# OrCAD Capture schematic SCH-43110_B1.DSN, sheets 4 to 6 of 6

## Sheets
4 3. MKW38A MCU: size C
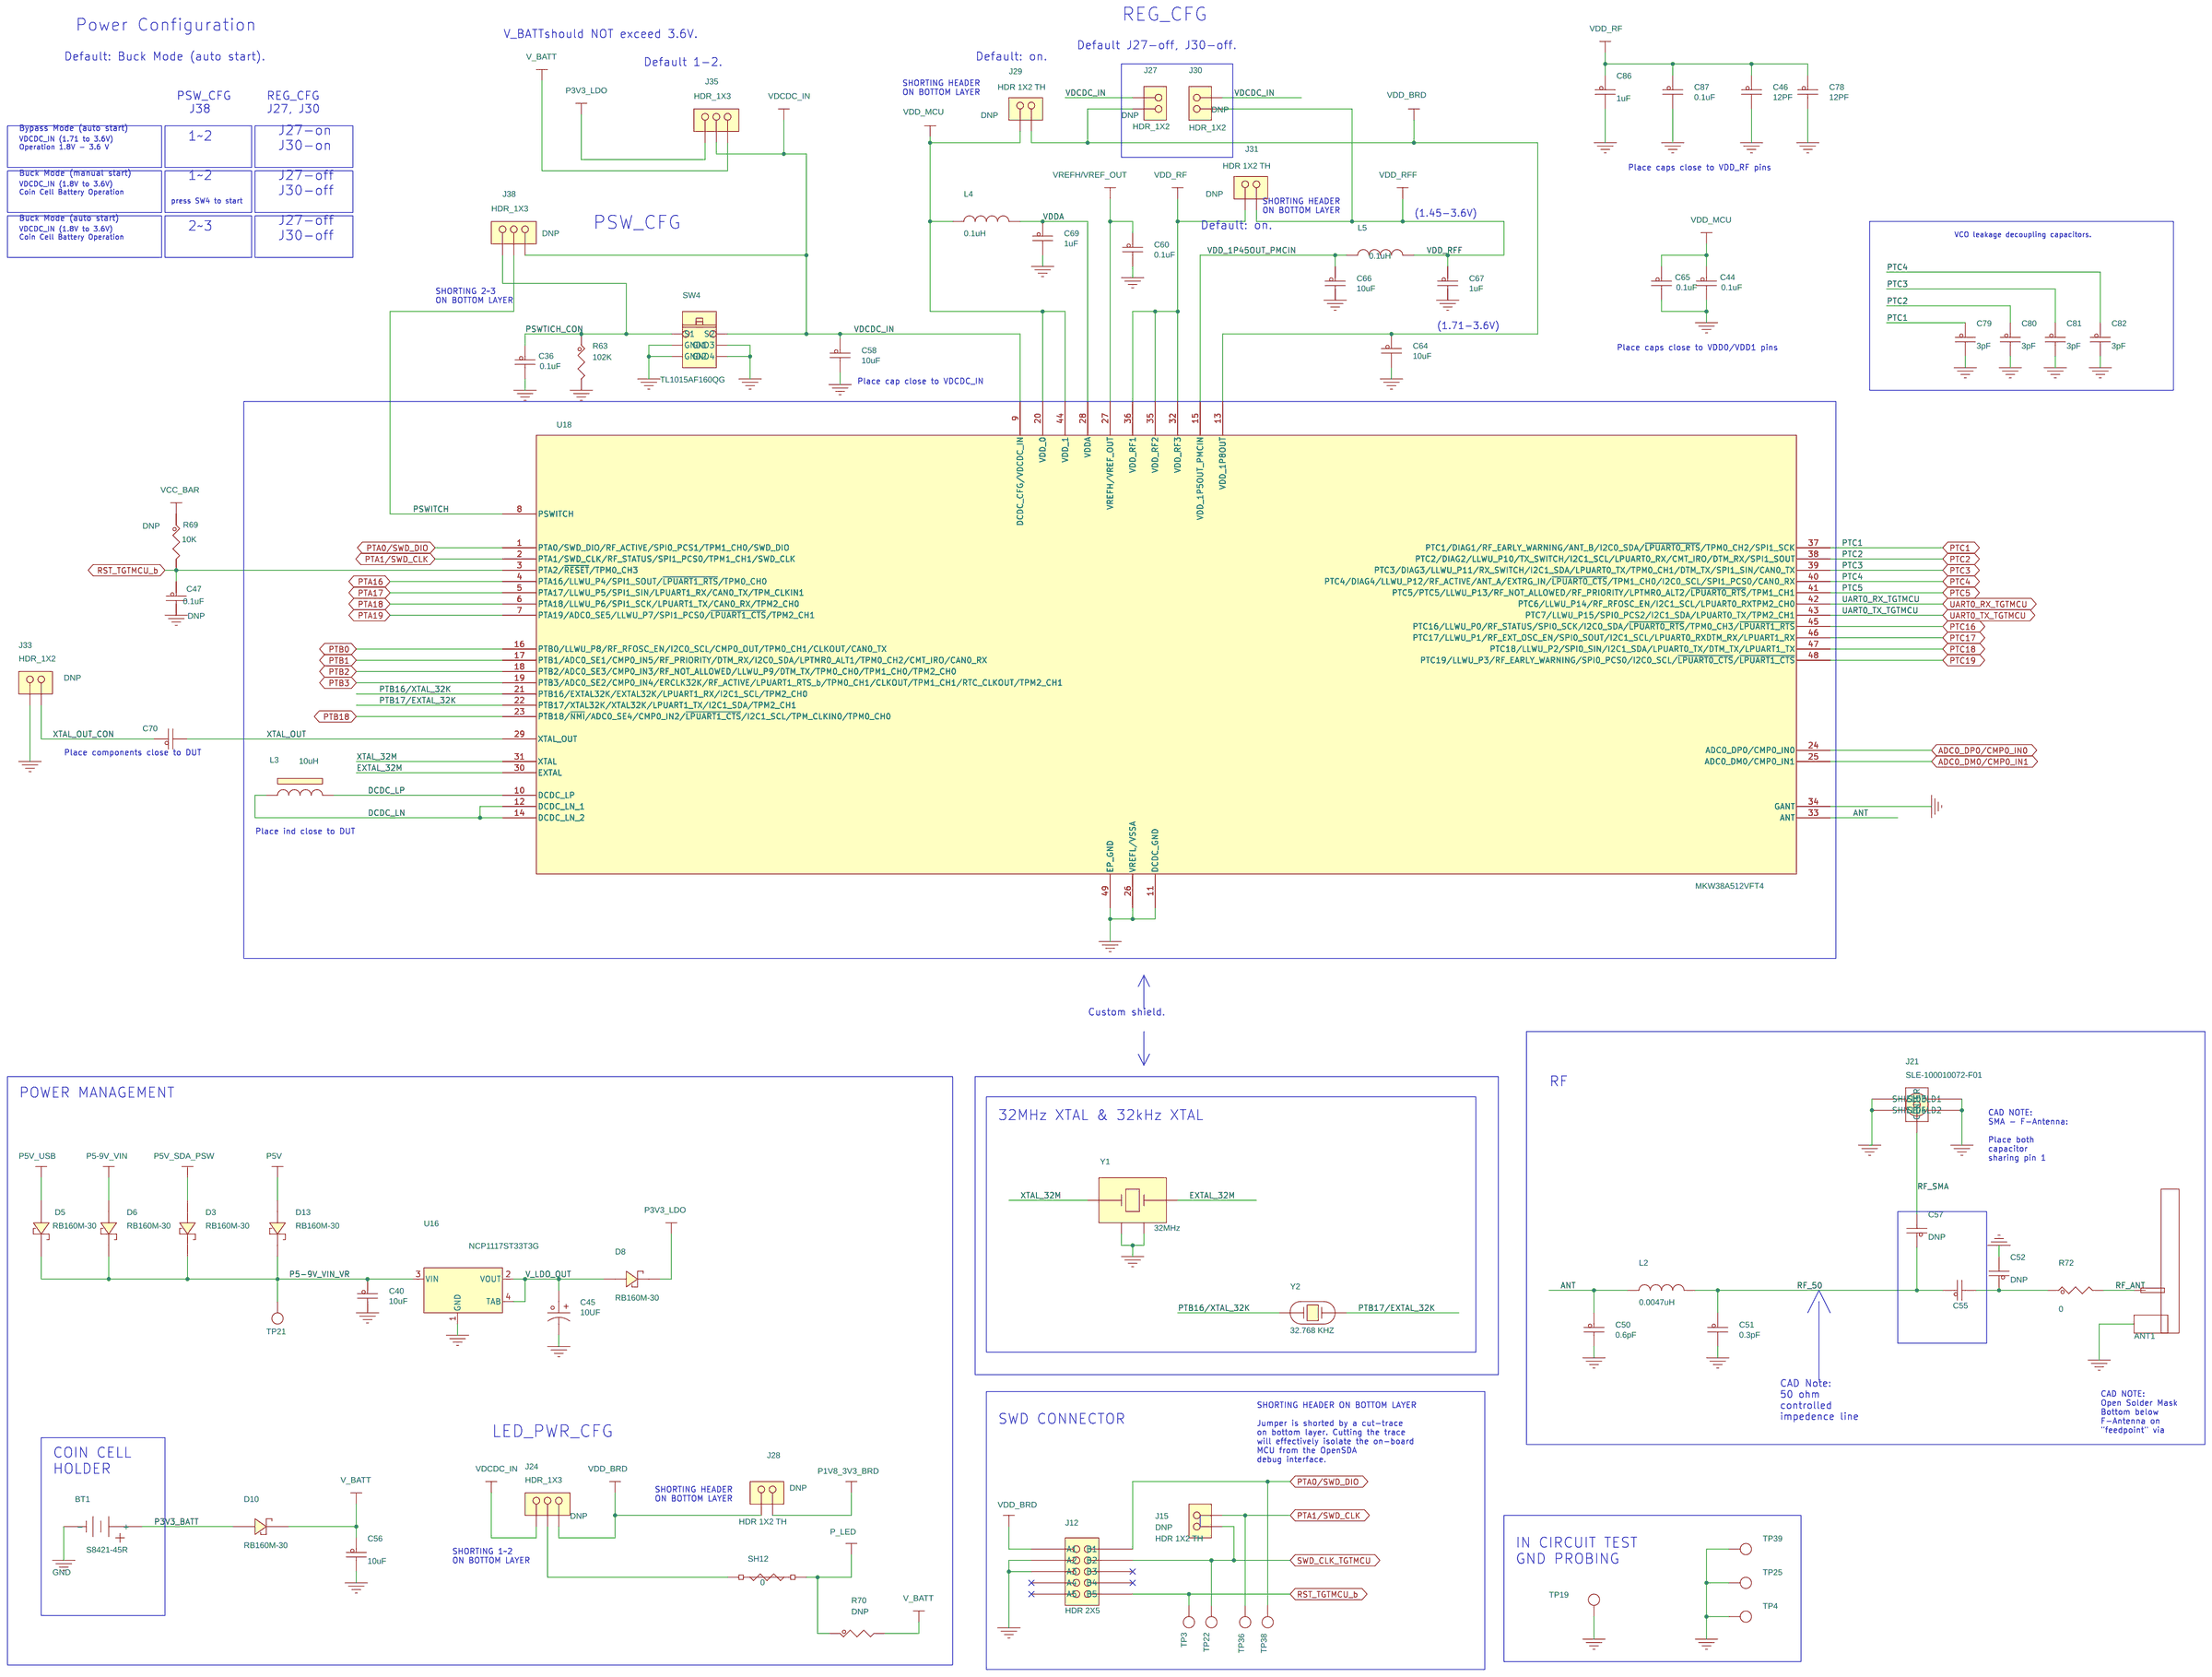
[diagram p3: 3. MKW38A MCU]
5 2. Block Diagram
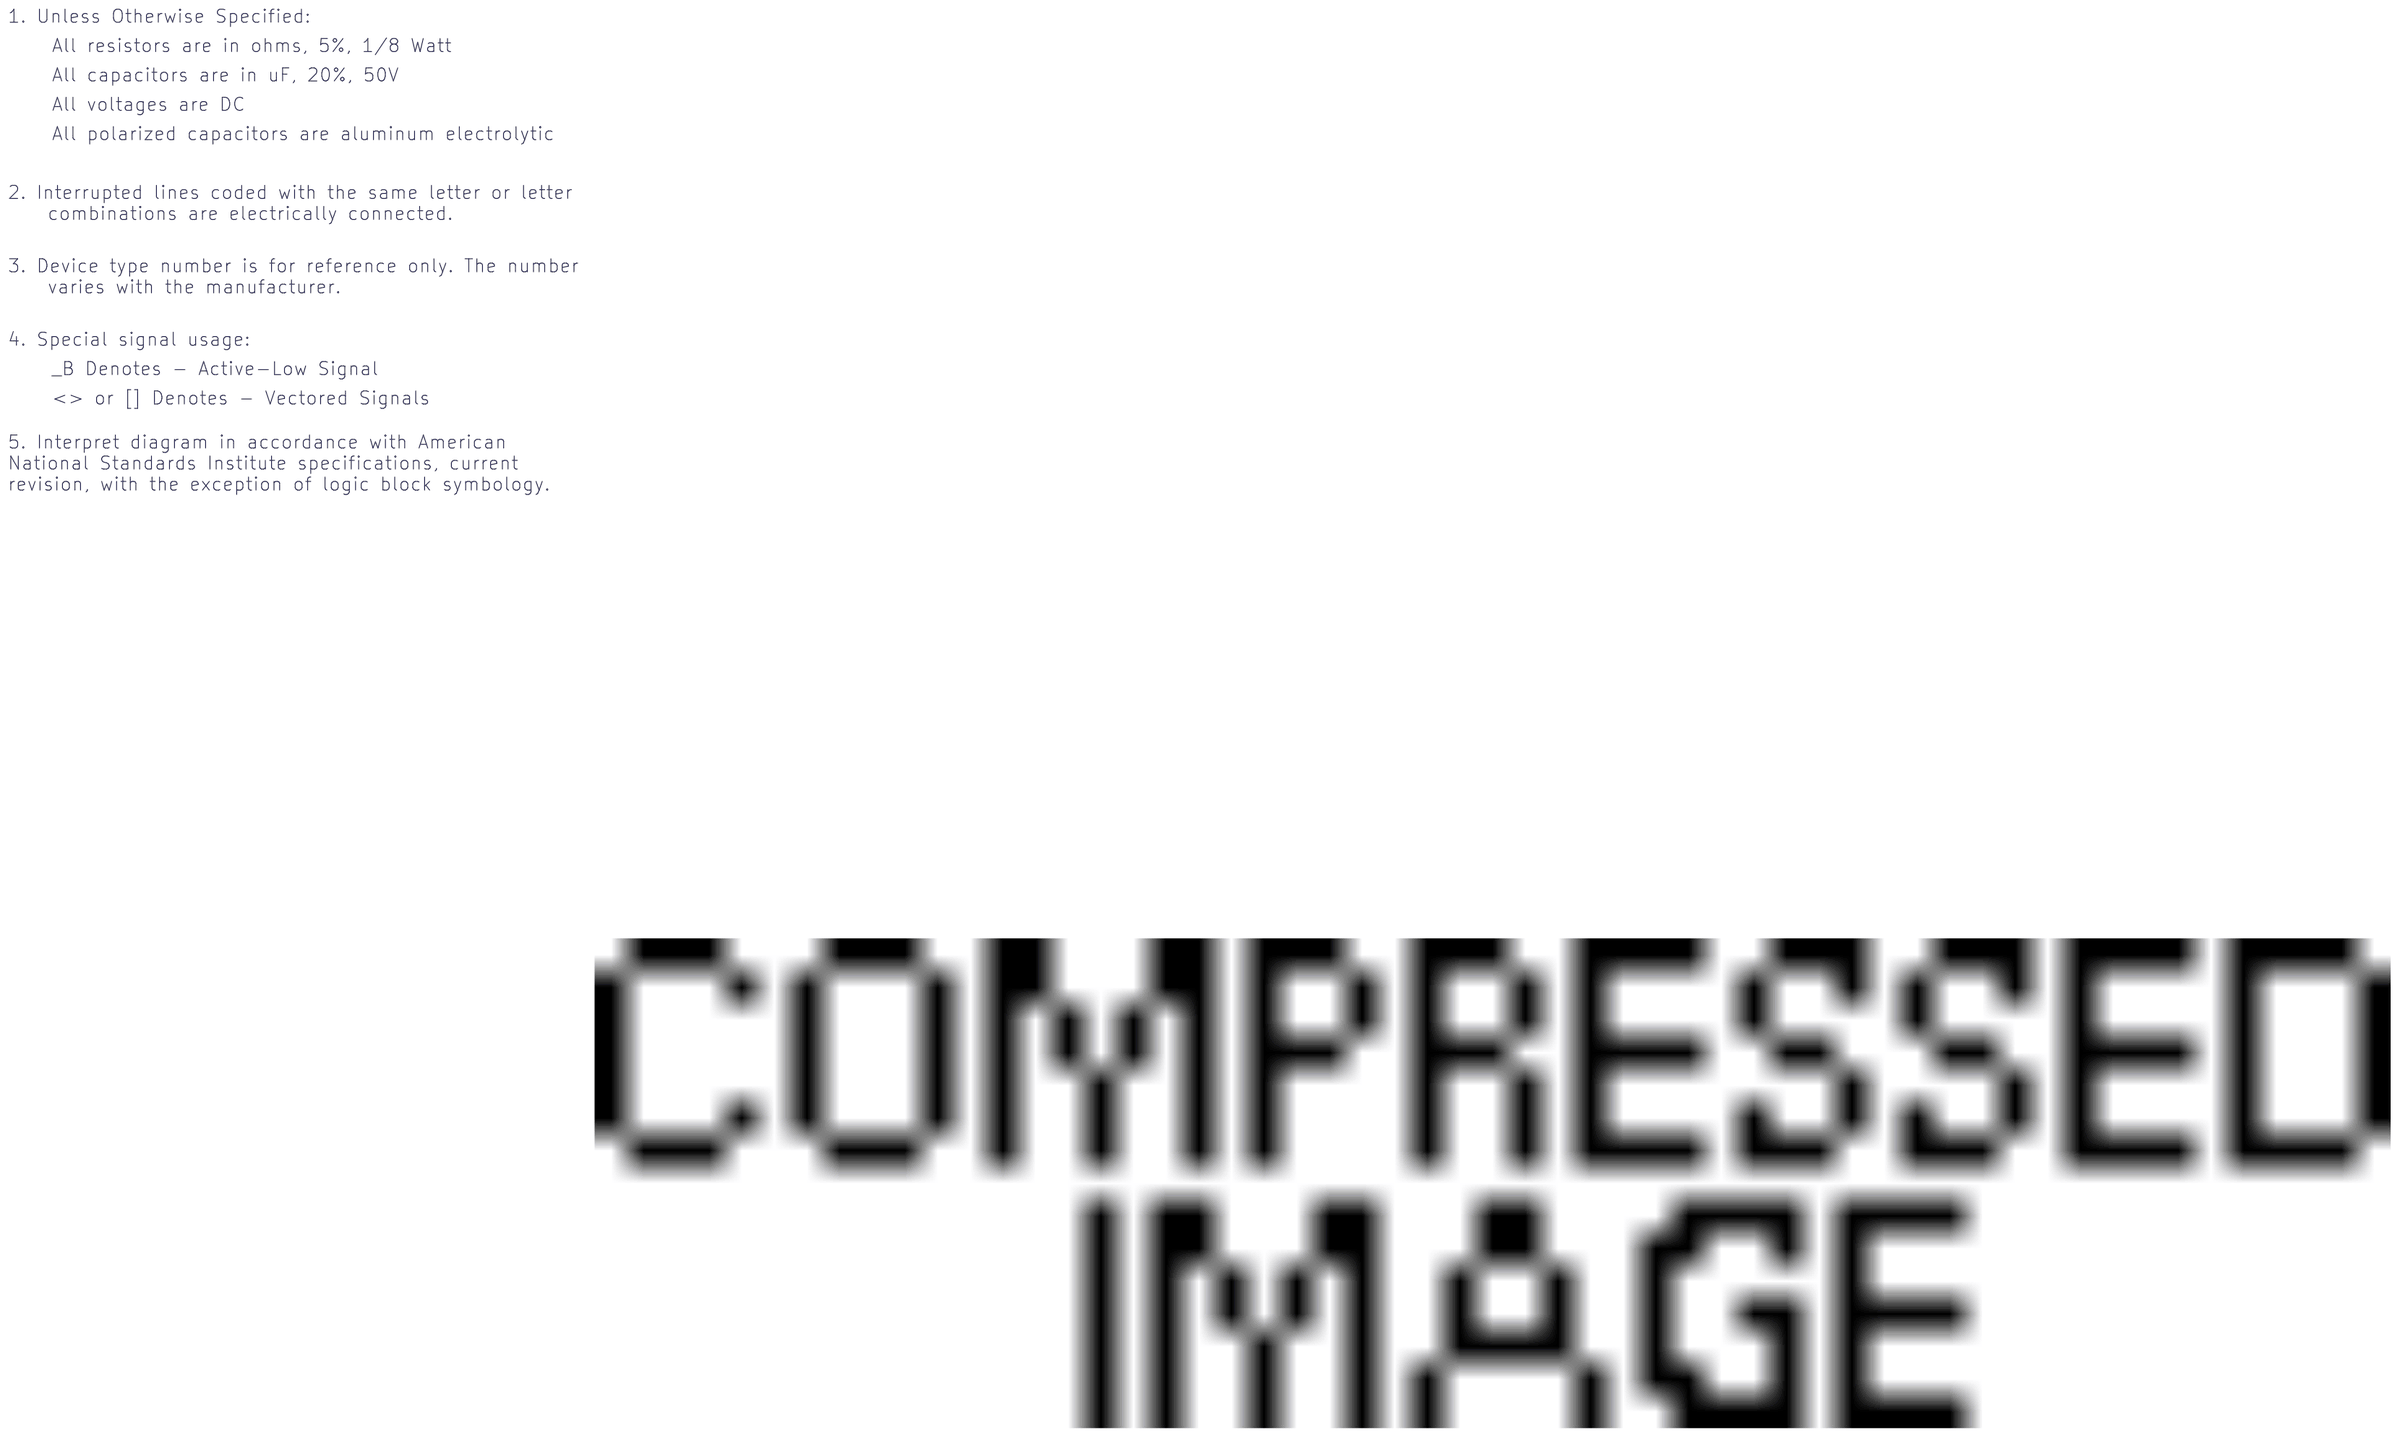
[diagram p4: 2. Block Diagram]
6 6. I/O Headers and Power Supply: size C
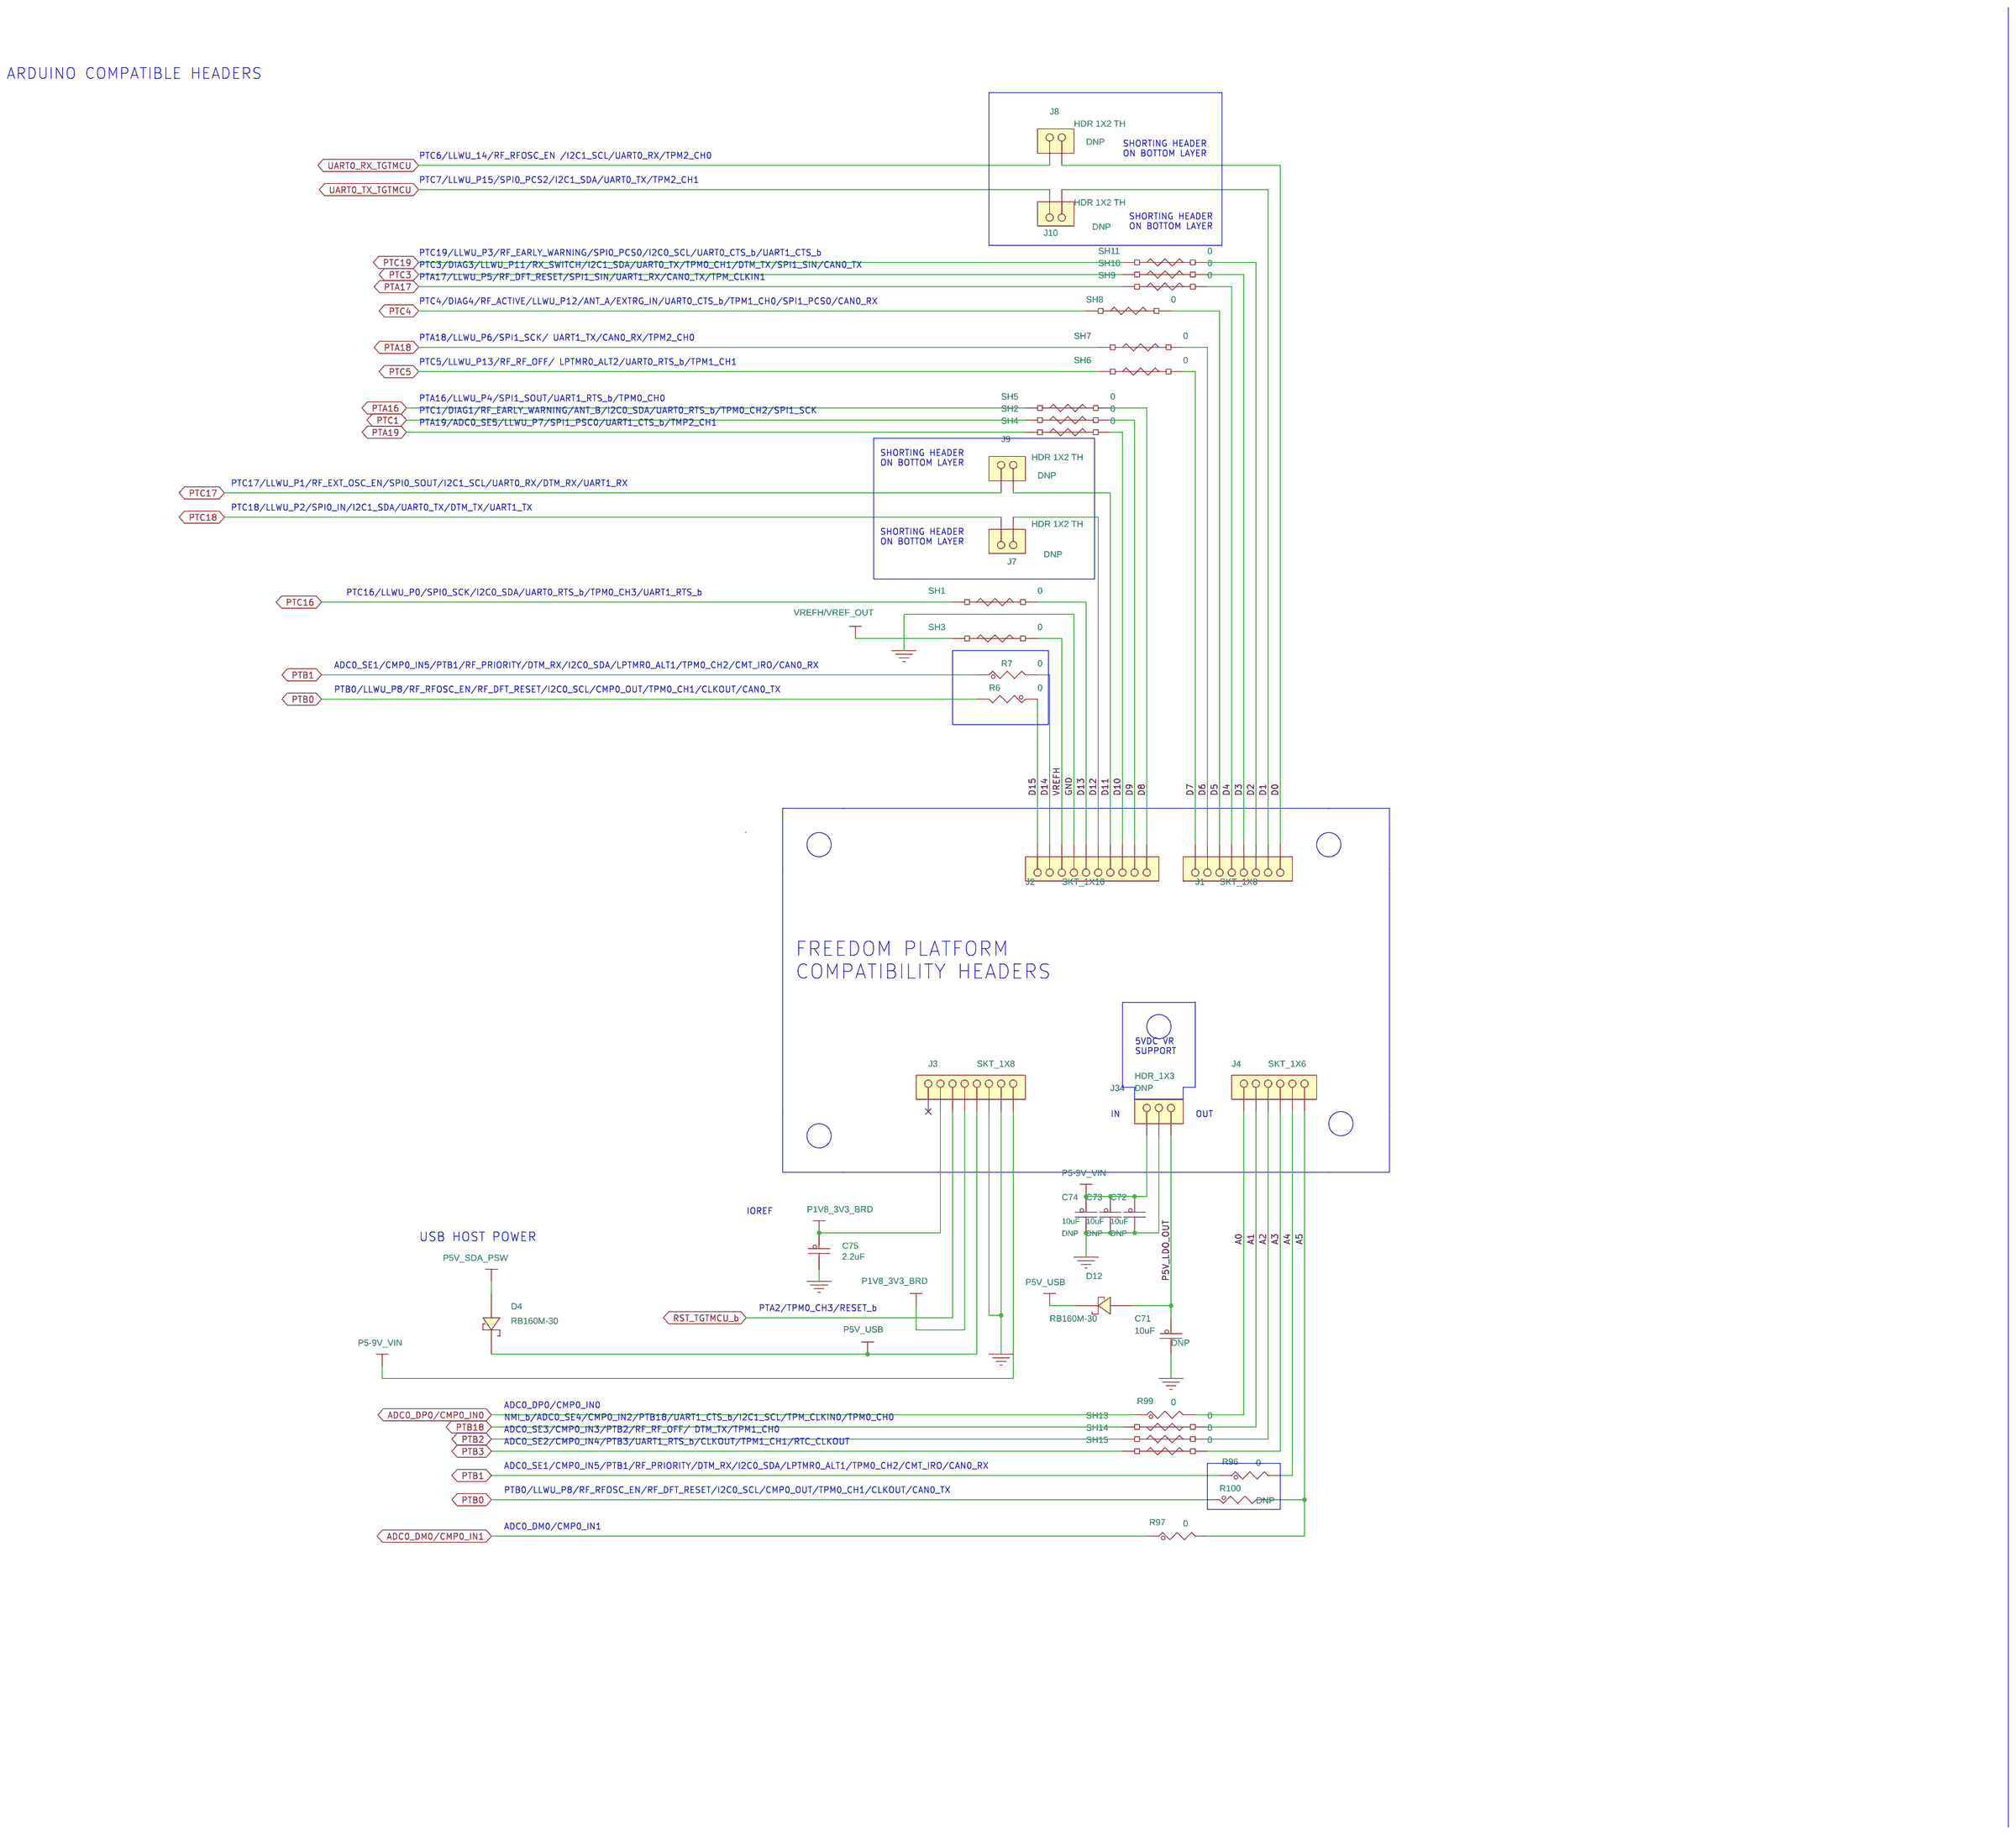
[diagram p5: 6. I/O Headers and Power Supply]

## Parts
sheet 3. MKW38A MCU
ANT1  F_Antenna  [f_antenna_dig528-2]
BT1  S8421-45R  [battery_holder_2032_sm]
C36  0.1uF  [CC0402_25]
C40  10uF  [CC0603_OV]
C44  0.1uF  [CC0402_25]
C45  10UF  [CC3216]
C46  12PF  [CC0402_25]
C47  0.1uF  [CC0402_25]
C50  0.6pF  [CC0402_25]
C51  0.3pF  [CC0402_25]
C52  10PF  [CC0402_25]
C55  10PF  [CC0402_25]
C56  10uF  [CC0603_OV]
C57  10PF  [CC0402_25]
C58  10uF  [CC0603_OV]
C60  0.1uF  [CC0402_25]
C64  10uF  [CC0603_OV]
C65  0.1uF  [CC0402_25]
C66  10uF  [CC0603_OV]
C67  1uF  [CC0402_25]
C69  1uF  [CC0402_25]
C70  10PF  [CC0402_25]
C78  12PF  [CC0402_25]
C79  3pF  [CC0402_25]
C80  3pF  [CC0402_25]
C81  3pF  [CC0402_25]
C82  3pF  [CC0402_25]
C86  1uF  [CC0402_25]
C87  0.1uF  [CC0402_25]
D3  RB160M-30  [pmdu_sod123]
D5  RB160M-30  [pmdu_sod123]
D6  RB160M-30  [pmdu_sod123]
D8  RB160M-30  [pmdu_sod123]
D10  RB160M-30  [pmdu_sod123]
D13  RB160M-30  [pmdu_sod123]
J12  HDR 2X5  [hdr_2X5_6x3_1p27mm_th]
J15  HDR 1X2 TH  [SH_HDR102_BOTTOM]
J21  SLE-100010072-F01  [con5_sma_7sq_sm]
J24  HDR_1X3  [HDR103]
J27  HDR_1X2  [hdr_1x2_2p54mm]
J28  HDR 1X2 TH  [SH_HDR102_BOTTOM]
J29  HDR 1X2 TH  [SH_HDR102_BOTTOM]
J30  HDR_1X2  [hdr_1x2_2p54mm]
J31  HDR 1X2 TH  [SH_HDR102_BOTTOM]
J33  HDR_1X2  [hdr_1x2_2p54mm]
J35  HDR_1X3  [HDR103]
J38  HDR_1X3  [HDR103]
L2  0.0047uH  [IND_0402]
L3  10uH  [ind_vls4012e]
L4  0.1uH  [IND_0402]
L5  0.1uH  [IND_0402]
R63  102K  [RC0402_25]
R69  10K  [RC0402_25]
R70  0  [RC0402_25]
R72  0  [RC0402_25]
SH12  0  [SH0603]
SW4  TL1015AF160QG  [sw2_spst_4x3_sm]
TP3  TPAD_030  [TPAD_030]
TP4  TPAD_030  [TPAD_030]
TP19  TESTLOOP_BLACK  [tp_th_063]
TP21  TPAD_040  [TPAD_040]
TP22  TPAD_030  [TPAD_030]
TP25  TPAD_030  [TPAD_030]
TP36  TPAD_030  [TPAD_030]
TP38  TPAD_030  [TPAD_030]
TP39  TPAD_030  [TPAD_030]
U16  NCP1117ST33T3G  [sot223]
U18  MKW38A512VFT4  [qfn_48_0p5_7x7_5p7ep]
Y1  32MHz  [xtal4_2p1x1p7mm_sm]
Y2  32.768 KHZ  [XTAL2-3P2X1P5-SM]
sheet 6. I/O Headers and Power Supply
C71  10uF  [CC0603_OV]
C72  10uF  [CC0603_OV]
C73  10uF  [CC0603_OV]
C74  10uF  [CC0603_OV]
C75  2.2uF  [CC0603_OV]
D4  RB160M-30  [pmdu_sod123]
D12  RB160M-30  [pmdu_sod123]
J1  SKT_1X8  [con_1x8_skt_2p54_th]
J2  SKT_1X10  [con_skt1x10_th]
J3  SKT_1X8  [con_1x8_skt_2p54_th]
J4  SKT_1X6  [con_skt1x6_th]
J7  HDR 1X2 TH  [SH_HDR102_BOTTOM]
J8  HDR 1X2 TH  [SH_HDR102_BOTTOM]
J9  HDR 1X2 TH  [SH_HDR102_BOTTOM]
J10  HDR 1X2 TH  [SH_HDR102_BOTTOM]
J34  HDR_1X3  [HDR103]
R6  0  [RC0603_OV]
R7  0  [RC0603_OV]
R96  0  [RC0603_OV]
R97  0  [RC0603_OV]
R99  0  [RC0603_OV]
R100  0  [RC0402_25]
SH1  0  [SH0402]
SH2  0  [SH0402]
SH3  0  [SH0402]
SH4  0  [SH0402]
SH5  0  [SH0402]
SH6  0  [SH0402]
SH7  0  [SH0402]
SH8  0  [SH0402]
SH9  0  [SH0402]
SH10  0  [SH0402]
SH11  0  [SH0402]
SH13  0  [SH0402]
SH14  0  [SH0402]
SH15  0  [SH0402]

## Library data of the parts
ANT1 = F_Antenna: PCB F ANTENNA, NO PART ORDER; AGILE_PN: 510-75678; CAD_APPROVED: Yes; HEIGHT: 0MM; MFG_NAME01: NOT A PART; MFG_PN01: NOT A PART; ROHS: Yes
BT1 = BATTERY: BATTERY HOLDER CR2032 SMD; AGILE_PN: 801-76278; CAD_APPROVED: Yes; HEIGHT: 5.5 MM; MFG_NAME01: HARWIN INC; Package Type: SMT; ROHS: Yes; Temp Range: -40° C to +105° C; Temp_Range: -40° C to +105° C
C36 C44 C60 C65 C87 = CAP_NP: CAP CER 0.1uF 50V 10% X7R 0402; AGILE_PN: 150-79069; CAD_APPROVED: Yes; FPLIST: CC0402_25,CC0402_HD,0402_CC; HEIGHT: 0.55MM; MFG_NAME01: TDK; MFG_PN01: C1005X7R1H104K050BE; ROHS: Yes; Tolerance: 10%; VOLTAGE: 50V
C40 C56 C58 C64 C66 = CAP_NP: CAP CER 10uF 16V 20% X5R 0603; AGILE_PN: 150-79092; CAD_APPROVED: Yes; FPLIST: CC0603_OV,CC0603,0603_CC; HEIGHT: 1mm; MFG_NAME01: TAIYO YUDEN; MFG_PN01: EMK107BBJ106MA-T; ROHS: Yes; Tolerance: 20%; VOLTAGE: 16V
C45 = CAP_POL: CAP TANT ESR=0.900 OHMS 10UF 10V 20% -- 3216-18; AGILE_PN: 150-75257; CAD_APPROVED: Yes; HEIGHT: 1.8MM; MFG_NAME01: AVX; MFG_PN01: TPSA106M010R0900; Package Size: 3216-18; Package Type: 7" T/R; ROHS: Yes; Tolerance: 20%; VOLTAGE: 10V
C46 C78 = CAP_NP: CAP CER 12PF 50V 5% C0G 0402; AGILE_PN: 150-75680; CAD_APPROVED: Yes; FPLIST: CC0402_25,CC0402_HD,0402_CC; HEIGHT: 0.55MM; MFG_NAME01: NIC COMPONENTS CORP; MFG_PN01: NMC0402NPO120J50TRPF; ROHS: Yes; Tolerance: 5%; VOLTAGE: 50V
C47 = CAP_NP: CAP CER 0.1uF 50V 10% X7R 0402; AGILE_PN: 150-79069; ASSY_OPT: DNP; CAD_APPROVED: Yes; FPLIST: CC0402_25,CC0402_HD,0402_CC; HEIGHT: 0.55MM; MFG_NAME01: TDK; MFG_PN01: C1005X7R1H104K050BE; ROHS: Yes; Tolerance: 10%; VOLTAGE: 50V
C50 = CAP_NP: CAP CER 0.6pF 50V 0.1pF C0G AEC-Q200 0402; AGILE_PN: 150-80681; CAD_APPROVED: Yes; FPLIST: CC0402_25,CC0402_HD,0402_CC; HEIGHT: 0.55MM; MFG_NAME01: Murata; MFG_PN01: GCM1555C1HR60BA16; Package Size: 0402; ROHS: Yes; Temp Range: -55°C to +125°C; Temp_Range: -55°C to +125°C; Tolerance: 0.1pF; VOLTAGE: 50V
C51 = CAP_NP: CAP CER 0.3pF 50V 0.1pF C0G AEC-Q200 0402; AGILE_PN: 150-80775; CAD_APPROVED: Yes; FPLIST: CC0402_25,CC0402_HD,0402_CC; HEIGHT: 0.55MM; MFG_NAME01: Murata Electronics; MFG_PN01: GCM1555C1HR30BA16D; Package Size: 0402 (1005 Metric); Package Type: Surface Mount, MLCC; ROHS: Yes; Rated Voltage: 50V; Temp Range: -55°C to +125°C; Tolerance: 0.1pF
C52 C57 = CAP_NP: CAP CER 10PF 50V 5% C0G 0402; AGILE_PN: 150-75265; ASSY_OPT: DNP; CAD_APPROVED: YES; FPLIST: CC0402_25,CC0402_HD,0402_CC; HEIGHT: 0.635MM; MFG_NAME01: AVX; MFG_PN01: 04025A100JAT2A; Package Size: 0402; Package Type: 7; ROHS: Yes; TOL: 5%; Tolerance: 5%; VOLTAGE: 50V
C55 C70 = CAP_NP: CAP CER 10PF 50V 5% C0G 0402; AGILE_PN: 150-75265; CAD_APPROVED: YES; FPLIST: CC0402_25,CC0402_HD,0402_CC; HEIGHT: 0.635MM; MFG_NAME01: AVX; MFG_PN01: 04025A100JAT2A; Package Size: 0402; Package Type: 7; ROHS: Yes; TOL: 5%; Tolerance: 5%; VOLTAGE: 50V
C67 C69 C86 = CAP_NP: CAP CER 1uF 25V 10% X6S AEC-Q200 0402; AGILE_PN: 150-80570; CAD_APPROVED: Yes; FPLIST: CC0402_25,CC0402_HD,0402_CC; HEIGHT: 0.6MM; MFG_NAME01: MURATA; MFG_PN01: GRT155C81E105KE13D; Package Size: 1.1x0.6x0.6MM; Package Type: 0402; ROHS: Yes; Temp Range: -55°C to +105°C; Temp_Range: -55°C to +105°C; Tolerance: 10%; VOLTAGE: 25V
C79-C82 = CAP_NP: CAP CER 3pF 50V ±0.25pF C0G AEC-Q200 0402; AGILE_PN: 150-80781; CAD_APPROVED: YES; FPLIST: CC0402_25,CC0402_HD,0402_CC; HEIGHT: 0.55 MM; MFG_NAME01: Murata Electronics; MFG_PN01: GCQ1555C1H3R0CB01D; Package Size: 0402 (1005 Metric); Package Type: Surface Mount, MLCC; ROHS: YES; Rated Voltage: 50V; Tolerance: 0.25pF
D3-D6 D8 D10 D12 D13 = DIODE_SCHTKY: DIODE SCH 1A 30V SOD123; AGILE_PN: 480-79681; CAD_APPROVED: Yes; HEIGHT: 0.9MM; MFG_NAME01: ROHM; MFG_PN01: RB160M-30TR; ROHS: Yes
J12 = CONN_HDR_5X2: HDR 2X5 TH 50MIL CTR 264H AU 91L; AGILE_PN: 210-81148; CAD_APPROVED: Yes; HEIGHT: 6.7MM; MFG_NAME01: LIANYI DIANZI; MFG_PN01: 333210S1411; ROHS: Yes
J7-J10 J15 J28 J29 J31 = CONN_HDR_2X1: HDR 1X2 TH 100MIL SP 339H AU 98L; AGILE_PN: 210-75439; ASSY_OPT: DNP; CAD_APPROVED: YES; FPLIST: HDR102,SH_HDR102_BOTTOM; HEIGHT: 8.71 MM; MFG_NAME01: SAMTEC; MFG_PN01: TSW-102-07-G-S; ROHS: Yes; Temp Range: -55°C to +125°C; Temp_Range: -55°C to +125°C
J21 = CONN_COAX_1P_F: CON 1 JACK SMA SKT 50 OHM SMT -- 418H AU; AGILE_PN: 211-79911; CAD_APPROVED: Yes; HEIGHT: 10.6MM; MFG_NAME01: DONGGUAN SENLING INDUSTRIAL CO. LTD; Package Type: SMA; ROHS: Yes
J24 J34 J38 = CONN_HDR_3X1: HDR 1X3 TH 100MIL SP 350H AU 118L; AGILE_PN: 210-81176; ASSY_OPT: DNP; CAD_APPROVED: Yes; HEIGHT: 8.9MM; MFG_NAME01: LIANYI DIANZI; MFG_PN01: 313103S1411; Package Size: 7p62x2p54x8p9mm; Package Type: TH; ROHS: Yes
J27 J30 J33 = CONN_HDR_2X1: HDR 1X2 TH 100MIL SP 347H AU 118L; AGILE_PN: 210-81145; ASSY_OPT: DNP; CAD_APPROVED: Yes; HEIGHT: 8.8 MM; MFG_NAME01: LIANYI DIANZI; MFG_PN01: 313102S1411; ROHS: Yes
J35 = CONN_HDR_3X1: HDR 1X3 TH 100MIL SP 350H AU 118L; AGILE_PN: 210-81176; CAD_APPROVED: Yes; HEIGHT: 8.9MM; MFG_NAME01: LIANYI DIANZI; MFG_PN01: 313103S1411; Package Size: 7p62x2p54x8p9mm; Package Type: TH; ROHS: Yes
L2 = INDUCTOR: IND -- 0.0047uH@100MHZ 700mA +/-0.3nH AEC-Q200 0402; AGILE_PN: 180-79018; CAD_APPROVED: Yes; FPLIST: IND_0402,0402_CC; HEIGHT: 0.55MM; MFG_NAME01: MURATA; MFG_PN01: LQG15HH4N7S02; ROHS: Yes; Temp Range: -55&#8451; to 125&#8451;; Temp_Range: -55&#8451; to 125&#8451;
L3 = IND_FERRITE: IND WW FER 10uH@1MHz 0.99A 20% 4012; AGILE_PN: 180-78215; CAD_APPROVED: Yes; HEIGHT: 1.2MM; MFG_NAME01: TDK; MFG_PN01: VLS4012ET-100M; PART_TYPE: FERRITE\BEAD; ROHS: Yes
L4 L5 = INDUCTOR: IND -- 0.1uH@100MHz 120mA 5% AEC-Q200 0402; AGILE_PN: TMP-CIP-2337; CAD_APPROVED: Yes; FPLIST: IND_0402,0402_CC; HEIGHT: 0.6MM; MFG_NAME01: MURATA; MFG_PN01: LQW15ANR10J0Z; PRE_APN: 180-79128; ROHS: Yes
R63 = RES: RES MF 102K 1/16W 1% HF 0402; AGILE_PN: 470-81192; CAD_APPROVED: Yes; FPLIST: RC0402_25,RC0402_HD,0402_CC; HEIGHT: 0.40 MM; MFG_NAME01: YAGEO AMERICA; MFG_PN01: RC0402FR-07102KL; ROHS: Yes; Tolerance: 1%; VOLTAGE: 50V
R69 = RES: RES MF 10K 1/16W 1% 0402; AGILE_PN: 470-80452; ASSY_OPT: DNP; CAD_APPROVED: Yes; FPLIST: RC0402_25,RC0402_HD,0402_CC; HEIGHT: 0.40 MM; MFG_NAME01: NIC COMPONENTS CORP; MFG_PN01: NRCL04F1002TRF; ROHS: Yes; Tolerance: 1%
R70 R100 = RES: RES MF ZERO OHM 1/16W 5% 0402; AGILE_PN: 470-75394; ASSY_OPT: DNP; CAD_APPROVED: Yes; FPLIST: RC0402_25,RC0402_HD,RC0402_X2,0402_CC; HEIGHT: 0.45 MM; MFG_NAME01: ROHM; MFG_PN01: MCR01MZPJ000; ROHS: Yes; Tolerance: 5%; VOLTAGE: 1/16W
R72 = RES: RES MF ZERO OHM 1/16W 5% 0402; AGILE_PN: 470-75394; CAD_APPROVED: Yes; FPLIST: RC0402_25,RC0402_HD,RC0402_X2,0402_CC; HEIGHT: 0.45 MM; MFG_NAME01: ROHM; MFG_PN01: MCR01MZPJ000; ROHS: Yes; Tolerance: 5%; VOLTAGE: 1/16W
SH12 = RES_SHORT-2: ZERO OHM CUT TRACE 0603 PADS; NO PART TO ORDER; AGILE_PN: 470-80018; CAD_APPROVED: Yes; FPLIST: SH0603,SH0603_CC,SH0603-X2_PIN1TO2,SH0603-X2_PIN2TO3; HEIGHT: 0.1MM; MFG_NAME01: LAYOUT ELEMENT ONLY; MFG_PN01: LAYOUT ELEMENT ONLY; ROHS: Yes
SW4 = SW_SPNO_2P_GND6P: SW SPST PB 50MA 12V SMT; AGILE_PN: 510-77720; CAD_APPROVED: Yes; HEIGHT: 2.4MM; MFG_NAME01: E SWITCH; ROHS: Yes
TP3 TP4 TP22 TP25 TP36 TP38 TP39 = TESTLOOP: TEST POINT PAD 30MIL DIA SMT, NO PART TO ORDER; AGILE_PN: 211-76642; CAD_APPROVED: Yes; HEIGHT: 0.1MM; MFG_NAME01: NOTACOMPONENT; MFG_PN01: NOTACOMPONENT; ROHS: Yes
TP19 = TESTLOOP: TEST POINT PC MULTI PURPOSE BLK TH; AGILE_PN: 210-79450; CAD_APPROVED: Yes; HEIGHT: 8.13MM; MFG_NAME01: KEYSTONE ELECTRONICS; MFG_PN01: 5011; ROHS: Yes
TP21 = TESTLOOP: TEST POINT PAD 40MIL DIA SMT, NO PART TO ORDER; AGILE_PN: 211-76643; CAD_APPROVED: Yes; HEIGHT: 0.1MM; MFG_NAME01: NOTACOMPONENT; MFG_PN01: NOTACOMPONENT; ROHS: Yes
U16 = LD1117AS18: IC VREG LDO 1A 3.3V SOT223; AGILE_PN: 312-80039; CAD_APPROVED: Yes; HEIGHT: 1.8MM; MFG_NAME01: ON SEMICONDUCTOR; ROHS: Yes; Temp Range: 0°C to +125°C; Temp_Range: 0°C to +125°C; VOLTAGE: 3.3V
U18 = MKW38A512VFT4_QFN48: IC MCU 2.4GHZ 512KB FLASH 48 MHz 1.71-3.6V QFN48; AGILE_PN: TMP-WF-34657; CAD_APPROVED: Yes; HEIGHT: 1 MM; MFG_NAME01: NXP SEMICONDUCTORS; PRE_APN: 344-02346; ROHS: Yes; VOLTAGE: 1.71-3.6V
Y1 = XTAL_13: XTAL 32MHz AEC0Q200 SMD 2016; AGILE_PN: 230-78273; CAD_APPROVED: Yes; HEIGHT: 0.5MM; MFG_NAME01: NDK; MFG_PN01: NX2016SA EXS00A-CS11775; ROHS: Yes; Temp Range: -40 to +125C; Temp_Range: -40 to +125C
Y2 = XTAL: XTAL 32.768kHZ FIXED -- AEC-Q200 SMT 3.2X1.5MM; AGILE_PN: 230-78318; CAD_APPROVED: Yes; HEIGHT: 0.9MM; MFG_NAME01: NDK; MFG_PN01: NX3215SA 32.768KHz EXS00A-MU01218; ROHS: Yes; Temp Range: -40 to 125C; Temp_Range: -40 to 125C
C71-C74 = CAP_NP: CAP CER 10uF 16V 20% X5R 0603; AGILE_PN: 150-79092; ASSY_OPT: DNP; CAD_APPROVED: Yes; FPLIST: CC0603_OV,CC0603,0603_CC; HEIGHT: 1mm; MFG_NAME01: TAIYO YUDEN; MFG_PN01: EMK107BBJ106MA-T; ROHS: Yes; Tolerance: 20%; VOLTAGE: 16V
C75 = CAP_NP: CAP CER 2.2UF 16V 10% X5R 0603; AGILE_PN: 150-75417; CAD_APPROVED: YES; FPLIST: CC0603_OV,CC0603,0603_CC; HEIGHT: 0.9 MM; MFG_NAME01: CAPAX TECHNOLOGIES INC.; MFG_PN01: 0603B225K160SNT; Package Size: 0603; ROHS: Yes; Tolerance: 10%; VOLTAGE: 16V
J1 J3 = CONN_HDR_8X1: CON 1X8 SKT TH 100MIL SP 343H AU 126L; AGILE_PN: 210-81494; CAD_APPROVED: Yes; HEIGHT: 8.7MM; MFG_NAME01: LIANYI DIANZI; MFG_PN01: 218108S1411; ROHS: Yes; Temp Range: -40C to +105C; Temp_Range: -40C to +105C
J2 = CONN_HDR_10X1: CON 1X10 SKT TH 100MIL SP 343H AU 126L; AGILE_PN: 210-81493; CAD_APPROVED: Yes; HEIGHT: 8.7MM; MFG_NAME01: LIANYI DIANZI; MFG_PN01: 218110S1411; ROHS: Yes; Temp Range: -40C to +105C; Temp_Range: -40C to +105C
J4 = CONN_HDR_6X1: CON 1X6 SKT TH 100MIL SP 343H AU 126L; AGILE_PN: 210-81495; CAD_APPROVED: Yes; HEIGHT: 8.7MM; MFG_NAME01: LIANYI DIANZI; MFG_PN01: 218106S1411; ROHS: Yes; Temp Range: -40C to +105C; Temp_Range: -40C to +105C
R6 R7 R96 R97 R99 = RES: RES MF ZERO OHM 1/10W -- 0603; AGILE_PN: 470-80866; CAD_APPROVED: Yes; FPLIST: RC0603_OV,RC0603,R603-X2,0603_CC; HEIGHT: 0.6MM; MFG_NAME01: WALSIN TECHNOLOGY CORP.; MFG_PN01: WR06X000PTL; ROHS: Yes; Temp Range: –55 °C to +155 °C; Temp_Range: –55 °C to +155 °C
SH1-SH11 SH13-SH15 = RES_SHORT-2: ZERO OHM CUT TRACE 0402 PADS; NO PART TO ORDER; AGILE_PN: 470-76449; CAD_APPROVED: Yes; FPLIST: SH0402,SH0402_CC; HEIGHT: 0.1 MM; MFG_NAME01: LAYOUT ELEMENT ONLY; MFG_PN01: LAYOUT ELEMENT ONLY; ROHS: Yes

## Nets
GND: ANT1.2(GND) BT1.2(-) C36.2 C40.2 C44.2 C45.2 C46.2 C47.2 C50.2 C51.2 C52.2 C56.2 C58.2 C60.2 C64.2 C65.2 C66.2 C67.2 C69.2 C71.2 C72.2 C73.2 C74.2 C75.2 C78.2 C79.2 C80.2 C81.2 C82.2 C86.2 C87.2 J2.7 J3.6 J3.7 J12.3(A2) J12.5(A3) J21.2(SHIELD2) J21.3(SHIELD1) J21.4(SHIELD3) J21.5(SHIELD4) J33.1 J34.2 R63.2 SW4.G1(GND1) SW4.G2(GND2) SW4.G3(GND3) SW4.G4(GND4) TP4.1(Pin1) TP19.1(Pin1) TP25.1(Pin1) TP39.1(Pin1) U16.1(GND) U18.11(DCDC_GND) U18.26(VREFL/VSSA) U18.34(GANT) U18.49(EP_GND) Y1.2 Y1.4 ; also on sheet 1 3
P1V8_3V3_BRD: C75.1 J3.2 J3.4 J28.2 ; also on sheet 1 3
P3V3_BATT: BT1.1(+) D10.A
P3V3_LDO: D8.C J35.1 ; also on sheet 1
P5V: D13.A ; also on sheet 1
P5V_LDO_OUT: C71.1 D12.A J34.3
P5V_SDA_PSW: D3.A D4.A ; also on sheet 3
P5V_USB: D4.C D5.A D12.C J3.5
VDD_1P45OUT_PMCIN: C66.1 L5.1 U18.15(VDD_1P5OUT_PMCIN)
VDD_BRD: C64.1 J12.1(A1) J24.3 J27.1 J28.1 J29.1 R69.1 U18.13(VDD_1P8OUT)
VDD_MCU: C44.1 C65.1 J29.2 L4.1 U18.20(VDD_0) U18.44(VDD_1)
VDD_RF: C46.1 C78.1 C86.1 C87.1 J31.2 U18.32(VDD_RF3) U18.35(VDD_RF2) U18.36(VDD_RF1)
VDD_RFF: C67.1 J30.2 J31.1 L5.2
VDDA: C69.1 L4.2 U18.28(VDDA)
A0: J4.1 R99.2
A1: J4.2 SH13.2
A2: J4.3 SH14.2
A3: J4.4 SH15.2
A4: J4.5 R96.2
A5: J4.6 R97.2 R100.2
ADC0_DM0/CMP0_IN1: R97.1 U18.25(ADC0_DM0/CMP0_IN1) ; also on sheet 1
ADC0_DP0/CMP0_IN0: R99.1 U18.24(ADC0_DP0/CMP0_IN0) ; also on sheet 1
ANT: C50.1 L2.1 U18.33(ANT)
D0: J1.1 J8.2
D1: J1.2 J10.2
D2: J1.3 SH11.2
D3: J1.4 SH10.2
D4: J1.5 SH9.2
D5: J1.6 SH8.2
D6: J1.7 SH7.2
D7: J1.8 SH6.2
D8: J2.1 SH5.2
D9: J2.2 SH2.2
D10: J2.3 SH4.2
D11: J2.4 J9.2
D12: J2.5 J7.2
D13: J2.6 SH1.2
D14: J2.9 R7.2
D15: J2.10 R6.1
DCDC_LN: L3.2 U18.12(DCDC_LN_1) U18.14(DCDC_LN_2)
DCDC_LP: L3.1 U18.10(DCDC_LP)
EXTAL_32M: U18.30(EXTAL) Y1.3
P5-9V_VIN: C72.1 C73.1 C74.1 D6.A J3.8 J34.1
P5-9V_VIN_VR: C40.1 D3.C D5.C D6.C D13.C TP21.1(Pin1) U16.3(VIN)
P_LED: R70.1 SH12.1 ; also on sheet 1
PSWITCH: J38.2 U18.8(PSWITCH)
PSWTICH_CON: C36.1 J38.1 R63.1 SW4.1(S1)
PTA0/SWD_DIO: J12.2(B1) TP38.1(Pin1) U18.1(PTA0/SWD_DIO/RF_ACTIVE/SPI0_PCS1/TPM1_CH0/SWD_DIO) ; also on sheet 3
PTA1/SWD_CLK: J15.1 TP36.1(Pin1) U18.2(PTA1/SWD_CLK/RF_STATUS/SPI1_PCS0/TPM1_CH1/SWD_CLK)
PTA16: SH5.1 U18.4(PTA16/LLWU_P4/SPI1_SOUT/~{LPUART1_RTS}/TPM0_CH0) ; also on sheet 1
PTA17: SH9.1 U18.5(PTA17/LLWU_P5/SPI1_SIN/LPUART1_RX/CAN0_TX/TPM_CLKIN1) ; also on sheet 1
PTA18: SH7.1 U18.6(PTA18/LLWU_P6/SPI1_SCK/LPUART1_TX/CAN0_RX/TPM2_CH0) ; also on sheet 1
PTA19: SH4.1 U18.7(PTA19/ADC0_SE5/LLWU_P7/SPI1_PCS0/~{LPUART1_CTS}/TPM2_CH1) ; also on sheet 1
PTB0: R6.2 R100.1 U18.16(PTB0/LLWU_P8/RF_RFOSC_EN/I2C0_SCL/CMP0_OUT/TPM0_CH1/CLKOUT/CAN0_TX) ; also on sheet 1
PTB1: R7.1 R96.1 U18.17(PTB1/ADC0_SE1/CMP0_IN5/RF_PRIORITY/DTM_RX/I2C0_SDA/LPTMR0_ALT1/TPM0_CH2/CMT_IRO/CAN0_RX) ; also on sheet 1
PTB2: SH14.1 U18.18(PTB2/ADC0_SE3/CMP0_IN3/RF_NOT_ALLOWED/LLWU_P9/DTM_TX/TPM0_CH0/TPM1_CH0/TPM2_CH0) ; also on sheet 1
PTB3: SH15.1 U18.19(PTB3/ADC0_SE2/CMP0_IN4/ERCLK32K/RF_ACTIVE/LPUART1_RTS_b/TPM0_CH1/CLKOUT/TPM1_CH1/RTC_CLKOUT/TPM2_CH1) ; also on sheet 1
PTB16/XTAL_32K: U18.21(PTB16/EXTAL32K/EXTAL32K/LPUART1_RX/I2C1_SCL/TPM2_CH0) Y2.1
PTB17/EXTAL_32K: U18.22(PTB17/XTAL32K/XTAL32K/LPUART1_TX/I2C1_SDA/TPM2_CH1) Y2.2
PTB18: SH13.1 U18.23(PTB18/~{NMI}/ADC0_SE4/CMP0_IN2/~{LPUART1_CTS}/I2C1_SCL/TPM_CLKIN0/TPM0_CH0) ; also on sheet 1
PTC1: C79.1 SH2.1 U18.37(PTC1/DIAG1/RF_EARLY_WARNING/ANT_B/I2C0_SDA/~{LPUART0_RTS}/TPM0_CH2/SPI1_SCK) ; also on sheet 1
PTC2: C80.1 U18.38(PTC2/DIAG2/LLWU_P10/TX_SWITCH/I2C1_SCL/LPUART0_RX/CMT_IRO/DTM_RX/SPI1_SOUT) ; also on sheet 1
PTC3: C81.1 SH10.1 U18.39(PTC3/DIAG3/LLWU_P11/RX_SWITCH/I2C1_SDA/LPUART0_TX/TPM0_CH1/DTM_TX/SPI1_SIN/CAN0_TX) ; also on sheet 1
PTC4: C82.1 SH8.1 U18.40(PTC4/DIAG4/LLWU_P12/RF_ACTIVE/ANT_A/EXTRG_IN/~{LPUART0_CTS}/TPM1_CH0/I2C0_SCL/SPI1_PCS0/CAN0_RX) ; also on sheet 1
PTC5: SH6.1 U18.41(PTC5/PTC5/LLWU_P13/RF_NOT_ALLOWED/RF_PRIORITY/LPTMR0_ALT2/~{LPUART0_RTS}/TPM1_CH1) ; also on sheet 1
PTC16: SH1.1 U18.45(PTC16/LLWU_P0/RF_STATUS/SPI0_SCK/I2C0_SDA/~{LPUART0_RTS}/TPM0_CH3/~{LPUART1_RTS}) ; also on sheet 1
PTC17: J9.1 U18.46(PTC17/LLWU_P1/RF_EXT_OSC_EN/SPI0_SOUT/I2C1_SCL/LPUART0_RXDTM_RX/LPUART1_RX) ; also on sheet 1
PTC18: J7.1 U18.47(PTC18/LLWU_P2/SPI0_SIN/I2C1_SDA/LPUART0_TX/DTM_TX/LPUART1_TX) ; also on sheet 1
PTC19: SH11.1 U18.48(PTC19/LLWU_P3/RF_EARLY_WARNING/SPI0_PCS0/I2C0_SCL/~{LPUART0_CTS}/~{LPUART1_CTS}) ; also on sheet 1
RF_50: C51.1 C55.1 C57.1 L2.2
RF_ANT: ANT1.1(Signal) R72.2
RF_SMA: C57.2 J21.1(CENTER)
RST_TGTMCU_b: C47.1 J3.3 J12.10(B5) R69.2 TP3.1(Pin1) U18.3(PTA2/~{RESET}/TPM0_CH3) ; also on sheet 1 3
SWD_CLK_TGTMCU: J12.4(B2) J15.2 TP22.1(Pin1) ; also on sheet 3
UART0_RX_TGTMCU: J8.1 U18.42(PTC6/LLWU_P14/RF_RFOSC_EN/I2C1_SCL/LPUART0_RXTPM2_CH0) ; also on sheet 3
UART0_TX_TGTMCU: J10.1 U18.43(PTC7/LLWU_P15/SPI0_PCS2/I2C1_SDA/LPUART0_TX/TPM2_CH1) ; also on sheet 3
V_BATT: C56.1 D10.C J35.3 R70.2
V_LDO_OUT: C45.1 D8.A U16.2(VOUT) U16.4(TAB)
V_MAIN: C58.1 J24.1 J27.2 J30.1 J35.2 J38.3 SW4.2(S2) U18.9(DCDC_CFG/VDCDC_IN)
VREFH: J2.8 SH3.2
VREFH/VREF_OUT: C60.1 SH3.1 U18.27(VREFH/VREF_OUT)
XTAL_32M: U18.31(XTAL) Y1.1
XTAL_OUT: C70.2 U18.29(XTAL_OUT)
XTAL_OUT_CON: C70.1 J33.2
N21519740: J24.2 SH12.2
N21837447: C52.1 C55.2 R72.1

Not connected (* = marked no-connect by the designer): J3 1*; J12 6(B3)* 7(A4)* 8(B4)* 9(A5)*

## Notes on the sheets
sheet 4
- REG_CFG
- Power Configuration
- V_BATTshould NOT exceed 3.6V.
- Default: Buck Mode (auto start).
- Default: on.
- Default J27-off, J30-off.
- Default 1-2.
- PSW_CFG
    J38
- REG_CFG
  J27, J30
- SHORTING HEADER
  ON BOTTOM LAYER
- Bypass Mode (auto start)
- 1~2
- J27-on
  J30-on
- VDCDC_IN (1.71 to 3.6V)
  Operation 1.8V - 3.6 V
- Buck Mode (manual start)
- 1~2
- J27-off
  J30-off
- Place caps close to VDD_RF pins
- VDCDC_IN (1.8V to 3.6V)
  Coin Cell Battery Operation
- press SW4 to start
- SHORTING HEADER
  ON BOTTOM LAYER
- (1.45-3.6V)
- Buck Mode (auto start)
- 2~3
- J27-off
  J30-off
- PSW_CFG
- Default: on.
- VDCDC_IN (1.8V to 3.6V)
  Coin Cell Battery Operation
- VCO leakage decoupling capacitors.
- SHORTING 2~3
  ON BOTTOM LAYER
- (1.71-3.6V)
- Place caps close to VDD0/VDD1 pins
- Place cap close to VDCDC_IN
- Place components close to DUT
- Place ind close to DUT
- Custom shield.
- POWER MANAGEMENT
- RF
- 32MHz XTAL & 32kHz XTAL
- CAD NOTE:
  SMA - F-Antenna:
  Place both
  capacitor
  sharing pin 1
- CAD Note:
  50 ohm
  controlled
  impedence line
- CAD NOTE:
  Open Solder Mask
  Bottom below
  F-Antenna on
  "feedpoint" via
- SHORTING HEADER ON BOTTOM LAYER
  Jumper is shorted by a cut-trace
  on bottom layer. Cutting the trace
  will effectively isolate the on-board
  MCU from the OpenSDA
  debug interface.
- SWD CONNECTOR
- LED_PWR_CFG
- COIN CELL
  HOLDER
- SHORTING HEADER
  ON BOTTOM LAYER
- IN CIRCUIT TEST
  GND PROBING
- SHORTING 1~2
  ON BOTTOM LAYER
sheet 5
- 1. Unless Otherwise Specified:
- All resistors are in ohms, 5%, 1/8 Watt
- All capacitors are in uF, 20%, 50V
- All voltages are DC
- All polarized capacitors are aluminum electrolytic
- 2. Interrupted lines coded with the same letter or letter
      combinations are electrically connected.
- 3. Device type number is for reference only. The number
      varies with the manufacturer.
- 4. Special signal usage:
- _B Denotes - Active-Low Signal
- <> or [] Denotes - Vectored Signals
- 5. Interpret diagram in accordance with American
  National Standards Institute specifications, current
  revision, with the exception of logic block symbology.
sheet 6
- ARDUINO COMPATIBLE HEADERS
- SHORTING HEADER
  ON BOTTOM LAYER
- PTC6/LLWU_14/RF_RFOSC_EN /I2C1_SCL/UART0_RX/TPM2_CH0
- PTC7/LLWU_P15/SPI0_PCS2/I2C1_SDA/UART0_TX/TPM2_CH1
- SHORTING HEADER
  ON BOTTOM LAYER
- PTC19/LLWU_P3/RF_EARLY_WARNING/SPI0_PCS0/I2C0_SCL/UART0_CTS_b/UART1_CTS_b
- PTC3/DIAG3/LLWU_P11/RX_SWITCH/I2C1_SDA/UART0_TX/TPM0_CH1/DTM_TX/SPI1_SIN/CAN0_TX
- PTA17/LLWU_P5/RF_DFT_RESET/SPI1_SIN/UART1_RX/CAN0_TX/TPM_CLKIN1
- PTC4/DIAG4/RF_ACTIVE/LLWU_P12/ANT_A/EXTRG_IN/UART0_CTS_b/TPM1_CH0/SPI1_PCS0/CAN0_RX
- PTA18/LLWU_P6/SPI1_SCK/ UART1_TX/CAN0_RX/TPM2_CH0
- PTC5/LLWU_P13/RF_RF_OFF/ LPTMR0_ALT2/UART0_RTS_b/TPM1_CH1
- PTA16/LLWU_P4/SPI1_SOUT/UART1_RTS_b/TPM0_CH0
- PTC1/DIAG1/RF_EARLY_WARNING/ANT_B/I2C0_SDA/UART0_RTS_b/TPM0_CH2/SPI1_SCK
- PTA19/ADC0_SE5/LLWU_P7/SPI1_PSC0/UART1_CTS_b/TMP2_CH1
- SHORTING HEADER
  ON BOTTOM LAYER
- PTC17/LLWU_P1/RF_EXT_OSC_EN/SPI0_SOUT/I2C1_SCL/UART0_RX/DTM_RX/UART1_RX
- PTC18/LLWU_P2/SPI0_IN/I2C1_SDA/UART0_TX/DTM_TX/UART1_TX
- SHORTING HEADER
  ON BOTTOM LAYER
- PTC16/LLWU_P0/SPI0_SCK/I2C0_SDA/UART0_RTS_b/TPM0_CH3/UART1_RTS_b
- ADC0_SE1/CMP0_IN5/PTB1/RF_PRIORITY/DTM_RX/I2C0_SDA/LPTMR0_ALT1/TPM0_CH2/CMT_IRO/CAN0_RX
- PTB0/LLWU_P8/RF_RFOSC_EN/RF_DFT_RESET/I2C0_SCL/CMP0_OUT/TPM0_CH1/CLKOUT/CAN0_TX
- FREEDOM PLATFORM
  COMPATIBILITY HEADERS
- 5VDC VR
  SUPPORT
- IN
- OUT
- IOREF
- USB HOST POWER
- PTA2/TPM0_CH3/RESET_b
- ADC0_DP0/CMP0_IN0
- NMI_b/ADC0_SE4/CMP0_IN2/PTB18/UART1_CTS_b/I2C1_SCL/TPM_CLKIN0/TPM0_CH0
- ADC0_SE3/CMP0_IN3/PTB2/RF_RF_OFF/ DTM_TX/TPM1_CH0
- ADC0_SE2/CMP0_IN4/PTB3/UART1_RTS_b/CLKOUT/TPM1_CH1/RTC_CLKOUT
- ADC0_SE1/CMP0_IN5/PTB1/RF_PRIORITY/DTM_RX/I2C0_SDA/LPTMR0_ALT1/TPM0_CH2/CMT_IRO/CAN0_RX
- PTB0/LLWU_P8/RF_RFOSC_EN/RF_DFT_RESET/I2C0_SCL/CMP0_OUT/TPM0_CH1/CLKOUT/CAN0_TX
- ADC0_DM0/CMP0_IN1
